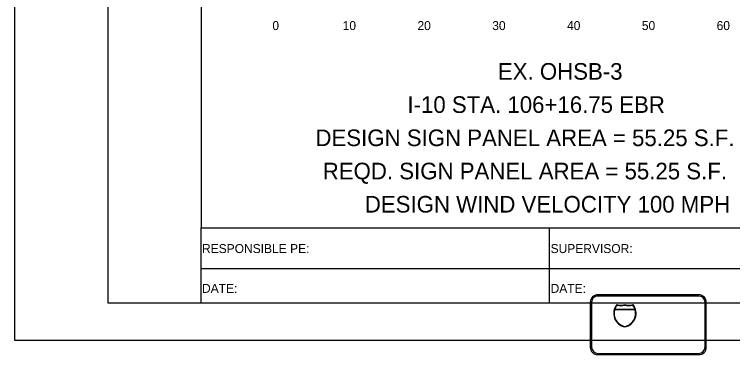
# Model space of a CAD drawing. Extents: x 2193008 to 2198143, y 1236112 to 1237864.
# Drawn here: x 2194857.9 to 2194953.9, y 1237116.1 to 1237161.6 of the extents above; entities that cross this region are included whole.
import ezdxf

# ---------------------------------------------------------------- set-up
doc = ezdxf.new("R2010")
doc.units = 0
for name, color, linetype in [('ANNO-TXT', 7, 'Continuous'), ('GSOUTLINE', 7, 'Continuous'), ('Level 55', 7, 'Continuous'), ('LIMT-CSLINE', 7, 'Continuous'), ('M-ROADS', 7, 'Continuous'), ('SHT-BNDRY', 7, 'Continuous')]:
    doc.layers.add(name, color=color, linetype=linetype)

msp = doc.modelspace()

# ---------------------------------------------------------------- linework, layer by layer
msp.add_lwpolyline([(2194882.86, 1237133.046), (2195182.86, 1237133.046), (2195182.86, 1237323.046), (2194882.86, 1237323.046)], close=True)
at = {"layer": 'GSOUTLINE'}
for p, q in [((2194949.375, 1237124.112), (2194935.871, 1237124.112)), ((2194949.375, 1237123.945), (2194935.871, 1237123.945)), ((2194934.871, 1237123.112), (2194934.871, 1237117.107)), ((2194935.038, 1237123.112), (2194935.038, 1237117.107)), ((2194950.208, 1237117.107), (2194950.208, 1237123.112)), ((2194950.375, 1237117.107), (2194950.375, 1237123.112)), ((2194935.871, 1237116.274), (2194949.375, 1237116.274)), ((2194935.871, 1237116.107), (2194949.375, 1237116.107))]:
    msp.add_line(p, q, dxfattribs=at)
for points in [[(2194940.867, 1237122.11), (2194938.12, 1237122.11)], [(2194938.138, 1237122.172), (2194940.849, 1237122.172)]]:
    msp.add_lwpolyline(points, dxfattribs=at)
for centre, major_axis, ratio, start_param, end_param in [((2194935.871, 1237123.112), (1, 0), 0.999829, 1.570796, 3.141593), ((2194935.871, 1237123.112), (0.833, 0), 0.999829, 1.570796, 3.141593), ((2194949.375, 1237123.112), (1, 0), 0.999829, 0, 1.570796), ((2194949.375, 1237123.112), (0.833, 0), 0.999829, 0, 1.570796), ((2194939.868, 1237121.636), (1.874, 0), 0.997059, 2.472588, 4.511032), ((2194939.868, 1237121.636), (1.812, 0), 0.997059, 2.495747, 2.84029), ((2194938.946, 1237124.583), (1.874, 0), 0.997059, 4.415842, 5.008936), ((2194938.946, 1237124.583), (1.937, 0), 0.997059, 4.438241, 4.999094), ((2194940.041, 1237124.583), (1.874, 0), 0.997059, 4.415842, 5.008936), ((2194939.119, 1237121.636), (1.874, 0), 0.997059, 4.913746, 6.95219), ((2194940.041, 1237124.583), (1.937, 0), 0.997059, 4.425684, 4.986537), ((2194939.119, 1237121.636), (1.812, 0), 0.997059, 0.301302, 0.645846), ((2194939.868, 1237121.636), (1.812, 0), 0.997059, 2.876207, 4.503988), ((2194939.119, 1237121.636), (1.812, 0), 0.997059, 4.92079, 6.548571), ((2194935.871, 1237117.107), (1, 0), 0.999829, 3.141593, 4.712389), ((2194935.871, 1237117.107), (0.833, 0), 0.999829, 3.141593, 4.712389), ((2194949.375, 1237117.107), (1, 0), 0.999829, 4.712389, 6.283185), ((2194949.375, 1237117.107), (0.833, 0), 0.999829, 4.712389, 6.283185)]:
    msp.add_ellipse(centre, major_axis=major_axis, ratio=ratio, start_param=start_param, end_param=end_param, dxfattribs=at)
at = {"layer": 'M-ROADS'}
msp.add_lwpolyline([(2194857.863, 1237118.036), (2195197.863, 1237118.036), (2195197.863, 1237338.036), (2194857.863, 1237338.036)], close=True, dxfattribs=at)
at = {"layer": 'SHT-BNDRY'}
for p, q in [((2194882.86, 1237123.036), (2194882.86, 1237133.046)), ((2194929.383, 1237133.046), (2194929.383, 1237123.036)), ((2194882.86, 1237127.646), (2195038.488, 1237127.646))]:
    msp.add_line(p, q, dxfattribs=at)
msp.add_lwpolyline([(2194870.363, 1237123.036), (2195192.863, 1237123.036), (2195192.863, 1237333.036), (2194870.363, 1237333.036)], close=True, dxfattribs=at)

# ---------------------------------------------------------------- texts
at = {"layer": 'ANNO-TXT'}
for s, p in [('RESPONSIBLE PE:', (2194882.954, 1237129.69)), ('SUPERVISOR:', (2194929.559, 1237129.69)), ('DATE:', (2194882.954, 1237124.371)), ('DATE:', (2194929.559, 1237124.371))]:
    msp.add_text(s, height=1.2, rotation=360, dxfattribs=at).set_placement(p)
at = {"layer": 'Level 55'}
for s, height, p in [('EX. OHSB-3', 2.2209, (2194922.512, 1237152.873)), ('I-10 STA. 106+16.75 EBR', 2.22092, (2194910.417, 1237148.431)), ('DESIGN SIGN PANEL AREA = 55.25 S.F.', 2.22092, (2194898.117, 1237143.989)), ('REQD. SIGN PANEL AREA = 55.25 S.F.', 2.22092, (2194899.093, 1237139.547)), ('DESIGN WIND VELOCITY 100 MPH', 2.22092, (2194904.721, 1237135.106))]:
    msp.add_text(s, height=height, dxfattribs=at).set_placement(p)
at = {"layer": 'LIMT-CSLINE'}
for s, p in [('0', (2194892.36, 1237159.506)), ('10', (2194901.76, 1237159.506)), ('20', (2194911.76, 1237159.506)), ('30', (2194921.76, 1237159.506)), ('40', (2194931.76, 1237159.506)), ('50', (2194941.76, 1237159.506)), ('60', (2194951.76, 1237159.506))]:
    msp.add_text(s, height=1.2, dxfattribs=at).set_placement(p)

doc.saveas('drawing.dxf')
